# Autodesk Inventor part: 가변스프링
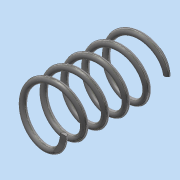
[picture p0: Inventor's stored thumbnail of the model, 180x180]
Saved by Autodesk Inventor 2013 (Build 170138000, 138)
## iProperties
Created: 2017-02
Part Number: 가변스프링
Material: 강철, 탄소
Document SubType Name: Modeling
Designer: dgall
Density: 7.87 g/cm^3
Mass: 6.51475 g
Surface Area: 16.8029 cm^2
Volume: 0.827795 cm^3
Author: dgall
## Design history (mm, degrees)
sketch "스케치1"
  geometry: L1 (0, 0)-(8.5, 0); L2 (19.466, 35)-(0, 35); L3 (0, 35)-(0, 0); C1 r 1 at (8.5, 0)
  constraints: 6 end point, 1 centre point, 1 coincident, 1 horizontal, 1 parallel, 1 vertical
  dimensions: "d0" = 2 diameter of C1; "d2" = 35 distance of L2.end L1.start (derived); "d3" = 17 diameter of L1.end L3
feature "코일1" sketch "스케치1" pitch "d4" = 10; turns "d6" = 5; dims "d5" = 35 (= d2), "d7" = 0, angle "d8" = 90 deg, angle "d9" = 90 deg, "d10" = 0, "d11" = 0
node "작업 평면1"
node "작업 평면2"
feature "분할1"
feature "분할2"
node "솔리드1"
other parameters: "d12" = 0, "d13" = 0
